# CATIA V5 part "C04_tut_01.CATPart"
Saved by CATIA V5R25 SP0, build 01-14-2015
Part number: Part1
Bounding box of the stored display mesh (mm): x -99.978 to 99.978, y -99.983 to 99.983, z 0 to 140
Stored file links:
  E:\ashutosh\Academics\Catia\CATIA V5-6R2013_partfiles\Tutorials_ver_2\C04_tut_01.CATPart
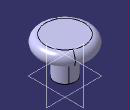
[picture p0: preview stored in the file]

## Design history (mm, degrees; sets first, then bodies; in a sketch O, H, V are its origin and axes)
Body1 (main body)
  Sketch1 on yz-plane, origin (0, 0, 0), H (0, 1, 0), V (0, 0, 1)
    line L1 (0, 0) -> (0, 140)
    line L2 (0, 140) -> (75, 140)
    point P2 (75, 140)
    arc A1 centre (75, 115) radius 25 from (75, 140) to (75, 90) cw
    line L3 (0, 0) -> (40, 0)
    line L4 (40, 0) -> (40, 70)
    line L5 (60, 90) -> (75, 90)
    arc A2 centre (60, 70) radius 20 from (40, 70) to (60, 90) cw
    distance P2 V = 75
    radius A2 = 20
    vertical: L1 V, L4 V
    horizontal: L2 H, L3 H
    tangency: A1 L2, L5 A1, A2 L4, A2 L5
  Shaft1: profile Sketch1, axis Sketch1.L1, angle 360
